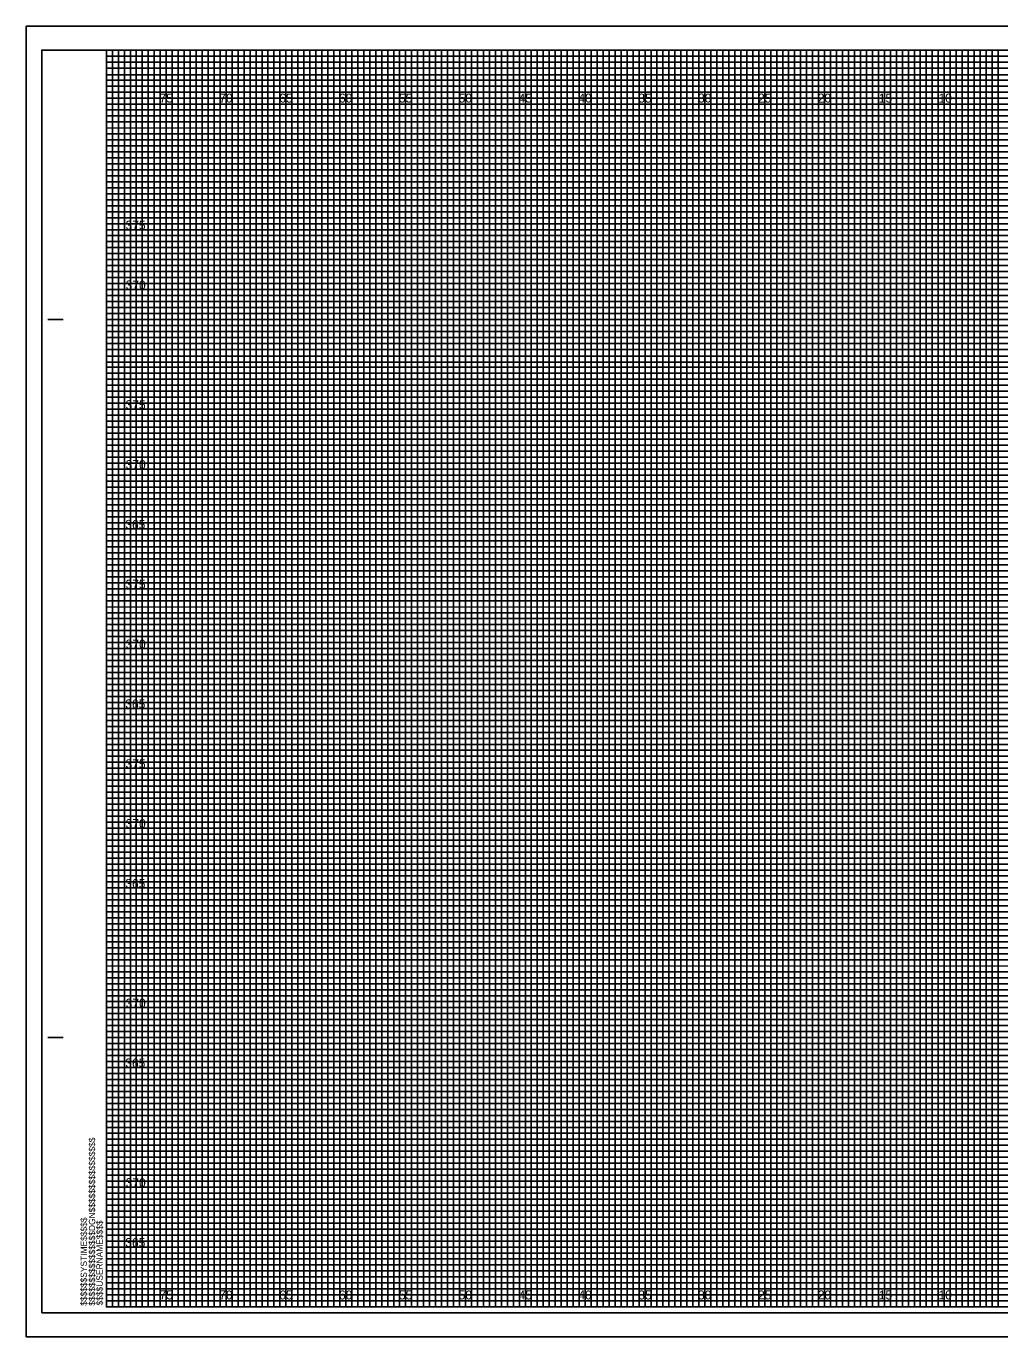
# Model space of a CAD drawing. Extents: x -7 to 162, y -2 to 327.
# Drawn here: x -6.7 to 74.6, y -2.5 to 107 of the extents above; entities that cross this region are included whole.
import ezdxf

# ---------------------------------------------------------------- set-up
doc = ezdxf.new("R2010")
doc.units = 0
for name, color, linetype in [('Exist Cross Section Cell', 7, 'Continuous'), ('Prop CMT Pvmt Course 1', 7, 'Continuous'), ('Prop CMT Pvmt Course 3', 7, 'Continuous'), ('Prop CMT Shld Paved Course 1', 7, 'Continuous'), ('Prop CMT Shld Paved Course 2', 7, 'Continuous'), ('Prop CMT Shld Paved Course 3', 7, 'Continuous'), ('Prop CMT Slope Grass', 7, 'Continuous'), ('Prop CMT Subgrade Earthwork', 7, 'Continuous'), ('Scratch_Level_3', 7, 'Continuous')]:
    doc.layers.add(name, color=color, linetype=linetype)

msp = doc.modelspace()

# ---------------------------------------------------------------- linework, layer by layer
at = {"layer": 'Prop CMT Pvmt Course 3'}
msp.add_lwpolyline([(-6.7, -2.5), (161.65, -2.5), (161.65, 107), (-6.7, 107)], close=True, dxfattribs=at)
at = {"layer": 'Prop CMT Shld Paved Course 1'}
for p, q in [((0, 104.5), (110.95, 104.5)), ((110.95, 103.99), (0, 103.99)), ((0, 103.99), (0, 103.5)), ((0, 103.5), (110.95, 103.5)), ((110.95, 102.95), (0, 102.95)), ((0, 102.95), (0, 102)), ((0, 102), (160, 102))]:
    msp.add_line(p, q, dxfattribs=at)
for points in [[(0, 101.5), (135, 101.5), (160, 101.5)], [(160, 101), (0, 101)], [(0, 100.5), (160, 100.5)], [(160, 99.5), (0, 99.5)], [(0, 99), (160, 99)], [(160, 98.5), (0, 98.49)], [(0, 98), (160, 98)], [(160, 97), (0, 97)], [(0, 96.5), (160, 96.5), (160, 96), (0, 96)], [(0, 95.5), (160, 95.5), (160, 94.5), (0, 94.5)], [(0, 94), (160, 94), (160, 93.5), (0, 93.5)], [(0, 93), (160, 93), (160, 92), (0, 92)], [(0, 91.5), (160, 91.5), (160, 91), (0, 91)], [(0, 90.5), (160, 90.5), (160, 89.5), (0, 89.5)], [(0, 89), (160, 89), (160, 88.5), (0, 88.5)], [(0, 88), (160, 88), (160, 86.97), (160, 86.5), (160, 86), (0, 86)], [(0, 87), (160, 87), (160, 86.5), (0, 86.5)], [(0, 85.5), (160, 85.5), (160, 84.5), (0, 84.51)], [(0, 84.51), (160, 84.5), (160, 84), (0, 84)], [(0, 83.5), (160, 83.5), (160, 83), (0, 83)], [(0, 82), (160, 82), (160, 81.5), (0, 81.5)], [(0, 81), (160, 81), (160, 80.5), (0, 80.5)], [(-0.04, 79.44), (160, 79.44), (160, 78.94), (-0.04, 78.94)], [(0, 78.5), (160, 78.5), (160, 78), (0, 78)], [(0, 77), (160, 77), (160, 76.5), (0, 76.5)], [(0, 76), (160, 76), (160, 75.5), (0, 75.5)], [(0, 74.5), (160, 74.5), (160, 74), (0, 74)], [(0, 73.5), (160, 73.5), (160, 73), (0, 73)], [(0, 72), (160, 72), (160, 71.5), (0, 71.5)], [(0, 71), (160, 71), (160, 70.5), (0, 70.5)], [(0, 69.5), (160, 69.5), (159.99, 68.99), (0, 69)], [(0, 68.5), (160, 68.5), (160, 68), (0, 68)], [(0, 67), (160, 67), (160, 66.5), (0, 66.5)], [(0, 66), (160, 66), (160, 65.5), (0, 65.5)], [(0, 64.5), (160, 64.5), (160, 64), (0, 64)], [(0, 63.5), (160, 63.5), (160, 63), (0, 63)], [(0, 62), (160, 62), (160, 61.5), (0, 61.5)], [(0, 61), (160, 61), (160, 60.5), (0, 60.5)], [(0, 59.5), (160, 59.5), (160, 59), (0, 59)], [(0, 58.5), (160.03, 58.45), (160, 58), (0, 58)], [(0, 57), (160, 57), (160, 56.5), (0, 56.5)], [(0, 56), (160, 56), (160, 55.5), (0, 55.5)], [(0, 54.5), (160, 54.5), (160, 54), (0, 54)], [(0, 53.5), (160, 53.5), (160, 53), (0, 53)], [(0, 52), (160, 52), (160, 51.5), (0, 51.5)], [(0, 51), (160, 51), (160, 50.5), (0, 50.5)], [(0, 49.5), (160, 49.5), (160, 49), (0, 49)], [(0, 48.5), (160, 48.5), (160, 48), (0, 48)], [(0, 47), (160, 47), (160, 46.5), (0, 46.5)], [(0, 46), (160, 46), (160, 45.5), (0, 45.5)], [(0, 44.5), (160, 44.5), (160, 44), (0, 44)], [(0, 43.5), (160, 43.5), (160, 43), (0, 43)], [(0, 42), (160, 42), (160, 41.5), (0, 41.5)], [(0, 41), (160, 41), (160, 40.5), (0, 40.5)], [(0, 39.5), (160, 39.5), (159.99, 38.99), (0, 39)], [(0, 38.5), (160, 38.5), (160, 38), (0, 38)], [(0, 37), (160, 37), (160, 36.5), (0, 36.5)], [(0, 36), (160, 36), (160, 35.5), (0, 35.5)], [(0, 34.5), (160, 34.5), (160, 34), (0, 34)], [(0, 33.5), (160, 33.5), (160, 33), (0, 33)], [(0, 32), (160, 32), (160, 31.5), (0, 31.5)], [(0, 31), (160, 31), (160, 30.5), (0, 30.5)], [(0, 29.5), (160, 29.5), (160, 29), (0, 29)], [(0, 28.5), (160.03, 28.46), (160, 28), (0, 28)], [(0, 27), (160, 27), (160, 26.5), (0, 26.5)], [(0, 26), (160, 26), (160, 25.5), (0, 25.5)], [(0, 24.5), (160, 24.5), (160, 24), (0, 24)], [(0, 23.5), (160, 23.5), (160, 23), (0, 23)], [(0, 22), (160, 22), (160, 21.5), (0, 21.5)], [(0, 21), (160, 21), (160, 20.5), (0, 20.5)], [(0, 19.5), (160, 19.5), (160, 19), (0, 19)], [(0, 18.5), (160, 18.5), (160, 18), (0, 18)], [(0, 17), (160, 17), (160, 16.5), (0, 16.5)], [(0, 16), (160, 16), (160, 15.5), (0, 15.5)], [(0, 14.5), (160, 14.5), (160, 14), (0, 14)], [(0, 13.5), (160, 13.5), (160, 13), (0, 13)], [(0, 12), (160, 12), (160, 11.5), (0, 11.5)], [(0, 11), (160, 11), (160, 10.5), (0, 10.5)], [(0, 9.5), (160, 9.5), (160, 9), (0, 9)], [(0, 8.5), (160, 8.5), (160, 8), (0, 8)], [(0, 7), (160, 7), (160, 6.5), (0, 6.5)], [(0, 6), (160, 6), (160, 5.5), (0, 5.5)], [(0, 4.5), (160, 4.5), (160, 4), (0, 4)], [(0, 3.5), (160, 3.5), (160, 3), (0, 3)], [(0, 2), (160, 2), (160, 1.5), (0, 1.5)], [(0, 1), (160, 1), (160, 0.5), (0, 0.5)]]:
    msp.add_lwpolyline(points, dxfattribs=at)
at = {"layer": 'Prop CMT Shld Paved Course 2'}
for p, q in [((-4.9, 82.5), (-3.65, 82.5)), ((-4.85, 82.5), (-3.6, 82.5)), ((-4.9, 22.5), (-3.65, 22.5)), ((-4.85, 22.5), (-3.6, 22.5)), ((0, 0), (0, 0)), ((0, 0), (0, 0)), ((0, 0), (0, 0)), ((0, 0), (0, 0)), ((0, 0), (0, 0)), ((0, 0), (0, 0)), ((0, 0), (0, 0))]:
    msp.add_line(p, q, dxfattribs=at)
msp.add_lwpolyline([(160, 105), (0, 105), (0, 0), (160, 0)], close=True, dxfattribs=at)
at = {"layer": 'Prop CMT Shld Paved Course 3'}
for points in [[(0, 0), (0.5, 0), (0.5, 105), (1, 105), (1, 0)], [(1, 0), (1.5, 0), (1.5, 105), (2, 105), (2, 0)], [(2.5, 0), (3, 0), (3, 105), (3.5, 105), (3.5, 0)], [(3.5, 0), (4, 0), (4, 105), (4.5, 105), (4.5, 0)], [(5, 0), (5.5, 0), (5.5, 105), (6, 105), (6, 0)], [(6, 0), (6.5, 0), (6.5, 105), (7, 105), (7, 0)], [(7.5, 0), (8, 0), (8, 105), (8.5, 105), (8.5, 0)], [(8.5, 0), (9, 0), (9, 105), (9.5, 105), (9.5, 0)], [(10, 0), (10.5, 0), (10.5, 105), (11, 105), (11, 0)], [(11, 0), (11.5, 0), (11.5, 105), (12, 105), (12, 0)], [(12.5, 0), (13, 0), (13, 105), (13.5, 105), (13.5, 0)], [(13.5, 0), (14, 0), (14, 105), (14.5, 105), (14.5, 0)], [(15, 0), (15.5, 0), (15.5, 105), (16, 105), (16, 0)], [(16, 0), (16.5, 0), (16.5, 105), (17, 105), (17, 0)], [(17.5, 0), (18, 0), (18, 105), (18.5, 105), (18.5, 0)], [(18.5, 0), (19, 0), (19, 105), (19.5, 105), (19.5, 0)], [(20, 0), (20.5, 0), (20.5, 105), (21, 105), (21, 0)], [(21, 0), (21.5, 0), (21.5, 105), (22, 105), (22, 0)], [(22.5, 0), (23, 0), (23, 105), (23.5, 105), (23.5, 0)], [(23.5, 0), (24, 0), (24, 105), (24.5, 105), (24.5, 0)], [(25, 0), (25.5, 0), (25.5, 105), (26, 105), (26, 0)], [(26, 0), (26.5, 0), (26.5, 105), (27, 105), (27, 0)], [(27.5, 0), (28, 0), (28, 105), (28.5, 105), (28.5, 0)], [(28.5, 0), (29, 0), (29, 105), (29.5, 105), (29.5, 0)], [(30, 0), (30.5, 0), (30.5, 105), (31, 105), (31, 0)], [(31, 0), (31.5, 0), (31.5, 105), (32, 105), (32, 0)], [(32.5, 0), (33, 0), (33, 105), (33.5, 105), (33.5, 0)], [(33.5, 0), (34, 0), (34, 105), (34.5, 105), (34.5, 0)], [(35, 0), (35.5, 0), (35.5, 105), (36, 105), (36, 0)], [(36, 0), (36.5, 0), (36.5, 105), (37, 105), (37, 0)], [(37.5, 0), (38, 0), (38, 105), (38.5, 105), (38.5, 0)], [(38.5, 0), (39, 0), (39, 105), (39.5, 105), (39.5, 0)], [(40, 0), (40.5, 0), (40.5, 105), (41, 105), (41, 0)], [(41, 0), (41.5, 0), (41.5, 105), (42, 105), (42, 0)], [(42.5, 0), (43, 0), (43, 105), (43.5, 105), (43.5, 0)], [(43.5, 0), (44, 0), (44, 105), (44.5, 105), (44.5, 0)], [(45, 0), (45.5, 0), (45.5, 105), (46, 105), (46, 0)], [(46, 0), (46.5, 0), (46.5, 105), (47, 105), (47, 0)], [(47.5, 0), (48, 0), (48, 105), (48.5, 105), (48.5, 0)], [(48.5, 0), (49, 0), (49, 105), (49.5, 105), (49.5, 0)], [(50, 0), (50.5, 0), (50.5, 105), (51, 105), (51, 0)], [(51, 0), (51.5, 0), (51.5, 105), (52, 105), (52, 0)], [(52.5, 0), (53, 0), (53, 105), (53.5, 105), (53.5, 0)], [(53.5, 0), (54, 0), (54, 105), (54.5, 105), (54.5, 0)], [(55, 0), (55.5, 0), (55.5, 105), (56, 105), (56, 0)], [(56, 0), (56.5, 0), (56.5, 105), (57, 105), (57, 0)], [(57.5, 0), (58, 0), (58, 105), (58.5, 105), (58.5, 0)], [(58.5, 0), (59, 0), (59, 105), (59.5, 105), (59.5, 0)], [(60, 0), (60.5, 0), (60.5, 105), (61, 105), (61, 0)], [(61, 0), (61.5, 0), (61.5, 105), (62, 105), (62, 0)], [(62.5, 0), (63, 0), (63, 105), (63.5, 105), (63.5, 0)], [(63.5, 0), (64, 0), (64, 105), (64.5, 105), (64.5, 0)], [(65, 0), (65.5, 0), (65.5, 105), (66, 105), (66, 0)], [(66, 0), (66.5, 0), (66.5, 105), (67, 105), (67, 0)], [(67.5, 0), (68, 0), (68, 105), (68.5, 105), (68.5, 0)], [(68.5, 0), (69, 0), (69, 105), (69.5, 105), (69.5, 0)], [(70, 0), (70.5, 0), (70.5, 105), (71, 105), (71, 0)], [(71, 0), (71.5, 0), (71.5, 105), (72, 105), (72, 0)], [(72.5, 0), (73, 0), (73, 105), (73.5, 105), (73.5, 0)], [(73.5, 0), (74, 0), (74, 105), (74.5, 105), (74.5, 0)]]:
    msp.add_lwpolyline(points, dxfattribs=at)
at = {"layer": 'Prop CMT Slope Grass'}
for points in [[(0, 105), (2.5, 105), (2.5, 0), (7.5, 0), (7.5, 105), (12.5, 105), (12.5, 0), (17.5, 0), (17.5, 105), (22.5, 105), (22.5, 0), (27.5, 0), (27.5, 105), (32.5, 105), (32.5, 0), (37.5, 0), (37.5, 105), (42.5, 105), (42.5, 0), (47.5, 0), (47.5, 105), (52.5, 105), (52.5, 0), (57.5, 0), (57.5, 105), (62.5, 105), (62.5, 0), (67.5, 0), (67.5, 105), (72.5, 105), (72.5, 0), (77.5, 0)], [(0, 102.5), (137.5, 102.5)], [(0, 92.5), (160, 92.5), (160, 102.5)], [(160, 97.5), (0, 97.5)], [(0, 82.5), (160, 82.5), (160, 87.5), (0, 87.5)], [(0, 72.5), (160, 72.5), (160, 77.5), (0, 77.5)], [(0, 62.5), (160, 62.5), (160, 67.5), (0, 67.5)], [(0, 52.5), (160, 52.5), (160, 57.5), (0, 57.5)], [(0, 42.5), (160, 42.5), (160, 47.5), (0, 47.5)], [(0, 32.5), (160, 32.5), (160, 37.5), (0, 37.5)], [(0, 22.5), (160, 22.5), (160, 27.5), (0, 27.5)], [(0, 12.5), (160, 12.5), (160, 17.5), (0, 17.5)], [(0, 2.5), (160, 2.5), (160, 7.5), (0, 7.5)]]:
    msp.add_lwpolyline(points, dxfattribs=at)
at = {"layer": 'Prop CMT Subgrade Earthwork'}
msp.add_lwpolyline([(-5.4, -0.5), (161.2, -0.5), (161.2, 105), (-5.4, 105)], close=True, dxfattribs=at)
at = {"layer": 'Scratch_Level_3'}
for p, q in [((5, 105), (0, 105)), ((5, 0), (5, 105)), ((15, 105), (10, 105)), ((10, 105), (10, 0)), ((15, 0), (15, 105)), ((25, 105), (20, 105)), ((20, 105), (20, 0)), ((25, 0), (25, 105)), ((35, 105), (30, 105)), ((30, 105), (30, 0)), ((35, 0), (35, 105)), ((45, 105), (40, 105)), ((40, 105), (40, 0)), ((45, 0), (45, 105)), ((55, 105), (50, 105)), ((50, 105), (50, 0)), ((55, 0), (55, 105)), ((65, 105), (60, 105)), ((60, 105), (60, 0)), ((65, 0), (65, 105)), ((75, 105), (70, 105)), ((70, 105), (70, 0)), ((10, 0), (5, 0)), ((20, 0), (15, 0)), ((30, 0), (25, 0)), ((40, 0), (35, 0)), ((60, 0), (55, 0)), ((70, 0), (65, 0)), ((50, 0), (45, 0))]:
    msp.add_line(p, q, dxfattribs=at)
for points in [[(160, 102.5), (160, 95), (0, 95)], [(0, 100), (160, 100)], [(0, 90), (160, 90), (160, 85), (0, 85)], [(0, 80), (160, 80), (160, 75), (0, 75)], [(0, 70), (160, 70), (160, 65), (0, 65)], [(0, 60), (160, 60), (160, 55), (0, 55)], [(0, 50), (160, 50), (160, 45), (0, 45)], [(0, 40), (160, 40), (160, 35), (0, 35)], [(0, 30), (160, 30), (160, 25), (0, 25)], [(0, 20), (160, 20), (160, 15), (0, 15)], [(0, 10), (160, 10), (160, 5), (0, 5)]]:
    msp.add_lwpolyline(points, dxfattribs=at)

# ---------------------------------------------------------------- texts
at = {"layer": 'Exist Cross Section Cell'}
for s, p in [('75', (4.44, 100.62)), ('70', (9.43, 100.62)), ('65', (14.44, 100.62)), ('60', (19.43, 100.62)), ('55', (24.44, 100.62)), ('50', (29.43, 100.62)), ('45', (34.44, 100.62)), ('40', (39.43, 100.62)), ('35', (44.44, 100.62)), ('30', (49.43, 100.62)), ('25', (54.44, 100.62)), ('20', (59.43, 100.62)), ('15', (64.53, 100.62)), ('10', (69.52, 100.62)), ('75', (4.44, 0.62)), ('70', (9.43, 0.62)), ('65', (14.44, 0.62)), ('60', (19.43, 0.62)), ('55', (24.44, 0.62)), ('50', (29.43, 0.62)), ('45', (34.44, 0.62)), ('40', (39.43, 0.62)), ('35', (44.44, 0.62)), ('30', (49.43, 0.62)), ('25', (54.44, 0.62)), ('20', (59.43, 0.62)), ('15', (64.53, 0.62)), ('10', (69.52, 0.62))]:
    msp.add_text(s, height=0.75, dxfattribs=at).set_placement(p)
at = {"layer": 'Prop CMT Pvmt Course 1'}
for s, p in [('375', (1.6, 90)), ('370', (1.61, 85)), ('375', (1.6, 75)), ('370', (1.61, 70)), ('365', (1.58, 65)), ('375', (1.6, 60)), ('370', (1.61, 55)), ('365', (1.58, 50)), ('375', (1.6, 45)), ('370', (1.61, 40)), ('365', (1.58, 35)), ('370', (1.61, 25)), ('365', (1.58, 20)), ('370', (1.61, 10)), ('365', (1.58, 5))]:
    msp.add_text(s, height=0.75, dxfattribs=at).set_placement(p)
at = {"layer": 'Prop CMT Shld Paved Course 2'}
for s, p in [('$$$$$$$$$$$$$$$$DGN$$$$$$$$$$$$$$$$', (-0.94, 0.09)), ('$$$$$$SYSTIME$$$$$', (-1.63, 0.09)), ('$$$$USERNAME$$$$', (-0.31, 0.12))]:
    msp.add_text(s, height=0.525, rotation=90, dxfattribs=at).set_placement(p)

doc.saveas('drawing.dxf')
